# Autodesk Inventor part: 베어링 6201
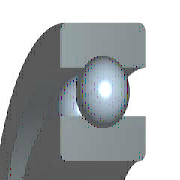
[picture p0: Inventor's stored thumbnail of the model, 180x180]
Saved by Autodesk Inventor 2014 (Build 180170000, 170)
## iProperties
Created: 2015-12
Part Number: 베어링 6201
Material: 강철, 연강
Description: 깊은 그루브 볼 베어링
Document SubType Name: Modeling
Standard: KS B 2023
Designer: mdu
Standards Organization: KS
Language: ko-KR
Size Designation: 6201 - 12 x 32 x 10
Categories: <MemberInstance><Categories><Category DisplayName="샤프트 부품" InternalName="7f7aeb1f-a693-4053-b835-cee3144e0d98" Mnemonic="SHFT"><Category DisplayName="베어링" Inter
Density: 7.86 g/cm^3
Mass: 32.7519 g
Surface Area: 42.5728 cm^2
Volume: 4.16691 cm^3
Appearance: 진녹색
Company: 한국ATC센터
IsCustomPart: 1
Author: mdu
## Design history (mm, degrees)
sketch "스케치" dims "d0" = 5.2 (= -0.26 x WD + 0.26 x BD)
  geometry: L1 (2.4, 11)-(7.6, 11); L2 (5, 11)-(5, 8.4); L3 (5, 11)-(5, 13.6); L4 (3.068, 9.26)-(0, 9.26); L5 (0, 6)-(10, 6); L6 (3.068, 12.74)-(0, 12.74); L7 (0, 16)-(10, 16); L8 (10, 6)-(10, 9.26); L9 (6.932, 9.26)-(10, 9.26); L10 (6.932, 12.74)-(10, 12.74); L11 (10, 16)-(10, 12.74); L12 (-1.4, 0)-(8.4, 0) reference; L13 (0, -0.3)-(0, 5.3) reference
  constraints: 22 end point, 4 point on line, 2 collinear, 2 perpendicular, 2 symmetric about line, 1 midpoint, 1 parallel, 14 other
  dimensions: "d9" = 12 diameter of L5 L12 (= WD); "d11" = 32 diameter of L7 L12 (= BD); "d12" = 10 distance between parallel lines of L8 L13 (= KB); "d13" = 18.52 diameter of L9 L12 (= 0.326 x BD + 0.674 x WD)
revolve "본체" stored, may be unused: angle "d6" = 90 deg
revolve "볼" stored, may be unused: angle "d7" = 90 deg
pattern_circular "IDS_ARRAYBALL[SIMPL:T]" dims angle "d3" = 360 deg
body "Solid1"
fillet "모깎기1" dims "d1" = 0.6 (= KRS)
other parameters: "WD" = 12 [user parameter; used in 5 equation terms], "BD" = 32 [user parameter; used in 5 equation terms], "KB" = 10 [user parameter; used in 1 equation term], "KRS" = 0.6 [user parameter; used in 1 equation term], "d4" = 0, "d5" = 0, "d8" = 0, "d14" = 0, "d15" = 0, "BBA" = 0 [user parameter], "BC0" = 3100000 [user parameter], "BC" = 6890000 [user parameter], "BR" = 16 (= 0.5 x BD) [user parameter], "WR" = 6 (= 0.5 x WD) [user parameter]
